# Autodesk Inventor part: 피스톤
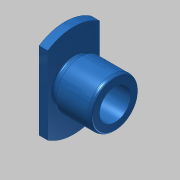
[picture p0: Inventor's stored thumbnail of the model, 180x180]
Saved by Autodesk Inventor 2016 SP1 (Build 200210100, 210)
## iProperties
Created: 2019-02
Part Number: 피스톤
Material: 알루미늄 6061
Document SubType Name: Modeling
Designer: mduedu
Density: 1 g/cm^3
Appearance: 청록색
Author: mduedu
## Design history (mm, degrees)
sketch "스케치1"
  geometry: C1 r 27 at (0, 0); 1 further point
  constraints: 1 centre point, 1 coincident
  dimensions: "d0" = 54 diameter of C1
extrude "돌출1" new body sketch "스케치1" distance "d1" = 5; taper "d2" = 0 deg
sketch "스케치2"
  geometry: L1 (-15, -27)-(15, -27); L2 (15, -27)-(15, 27); L3 (15, 27)-(-15, 27); L4 (-15, 27)-(-15, -27); L5 (-15, -27)-(15, 27); L6 (15, -27)-(-15, 27); C1 r 27 at (0, 0) reference; 1 further point
  constraints: 12 end point, 2 midpoint, 2 parallel, 1 horizontal, 1 perpendicular, 1 tangent
  dimensions: "d3" = 30 distance of L2.end L3.end
extrude "돌출2" sketch "스케치2" stored distance "d5" = 5; taper "d6" = 0 deg
sketch "스케치3"
  geometry: C1 r 12 at (0, 0); 1 further point
  constraints: 1 centre point, 1 coincident
  dimensions: "d7" = 24 diameter of C1
extrude "돌출3" join sketch "스케치3" distance "d8" = 4; taper "d9" = 0 deg
sketch "스케치4"
  geometry: C1 r 14 at (0, 0); 1 further point
  constraints: 1 centre point, 1 coincident
  dimensions: "d10" = 28 diameter of C1
extrude "돌출4" join sketch "스케치4" distance "d11" = 20; taper "d12" = 0 deg
fillet "모깎기1" dims "d13" = 1
chamfer "모따기1" distance "d14" = 1.8; stored, may be unused: second distance "d15" = 2, angle "d16" = 15 deg
fillet "모깎기2" dims "d17" = 1, "d18" = 2
sketch "스케치5"
  geometry: 2 further points
  constraints: 1 coincident
hole "구멍1" sketch "스케치5" at (0, 0) diameter "d19" = 18; stored, may be unused: countersink angle "d23" = 90 deg, drill point angle "d25" = 118 deg; dims "d20" = 6, "d21" = 4, "d22" = 2, "d24" = 15
node "솔리드1"
